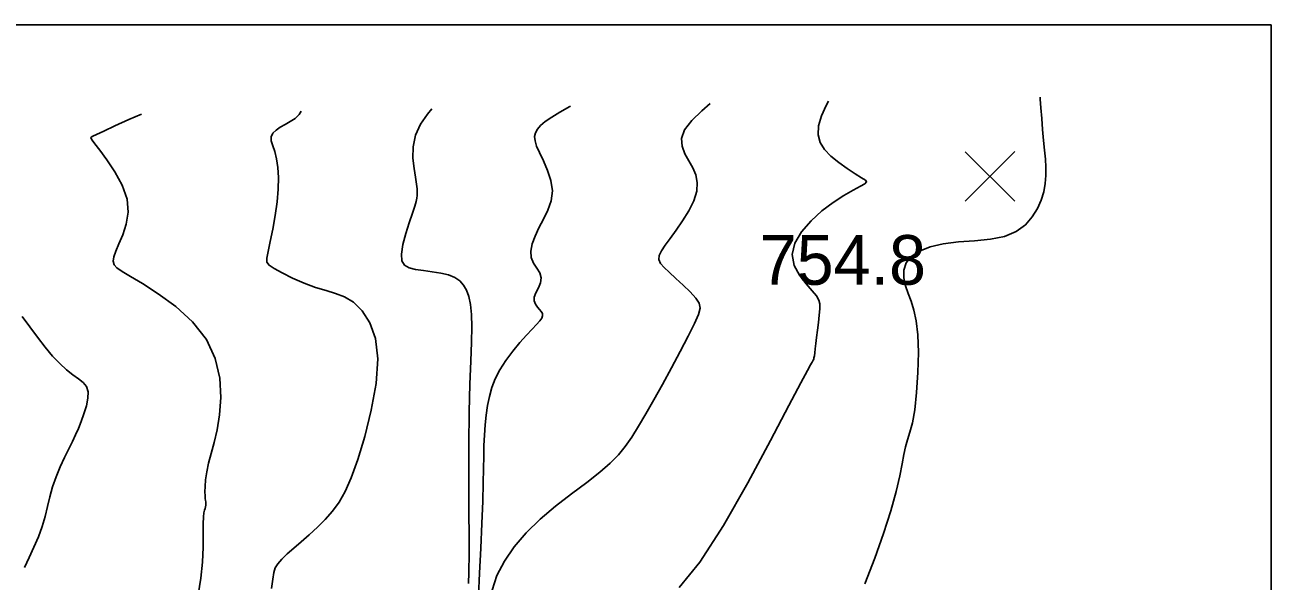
# Model space of a CAD drawing. Extents: x 2566142 to 2571431, y 418755 to 421584.
# Drawn here: x 2571031.7 to 2571407.8, y 421393.7 to 421561.7 of the extents above; entities that cross this region are included whole.
import ezdxf

# ---------------------------------------------------------------- set-up
doc = ezdxf.new("R2010")
doc.units = 0
for name, color, linetype in [('Contour_ADS_Major', 7, 'Continuous'), ('Contour_ADS_Minor', 7, 'Continuous'), ('Contour_ADS_Spot_Elevation', 7, 'Continuous'), ('Contour_ADS_State_Plane_Border', 7, 'Continuous')]:
    doc.layers.add(name, color=color, linetype=linetype)

# ---------------------------------------------------------------- blocks, each defined once
blk = doc.blocks.new('S750')
at = {"layer": 'Contour_ADS_Spot_Elevation'}
for p, q in [((-0.5, 0.498), (0.5, -0.498)), ((-0.498, -0.5), (0.498, 0.5))]:
    blk.add_line(p, q, dxfattribs=at)

msp = doc.modelspace()

# ---------------------------------------------------------------- linework, layer by layer
at = {"layer": 'Contour_ADS_Major'}
msp.add_lwpolyline([(2571168.56, 421389.26), (2571168.9, 421396.14), (2571169.26, 421403.66), (2571169.6, 421411.13), (2571169.87, 421417.87), (2571170.02, 421423.35), (2571170.11, 421427.74), (2571170.16, 421431.4), (2571170.24, 421434.66), (2571170.38, 421437.81), (2571170.6, 421440.88), (2571170.91, 421443.86), (2571171.33, 421446.73), (2571171.88, 421449.47), (2571172.63, 421452.15), (2571173.67, 421454.82), (2571175.07, 421457.55), (2571176.88, 421460.37), (2571178.95, 421463.17), (2571181.08, 421465.78), (2571183.08, 421468.04), (2571184.76, 421469.85), (2571186.11, 421471.24), (2571187.09, 421472.32), (2571187.7, 421473.17), (2571187.94, 421473.88), (2571187.86, 421474.51), (2571187.52, 421475.12), (2571186.99, 421475.76), (2571186.35, 421476.48), (2571185.76, 421477.32), (2571185.39, 421478.31), (2571185.42, 421479.47), (2571185.93, 421480.82), (2571186.68, 421482.3), (2571187.32, 421483.83), (2571187.53, 421485.34), (2571187.06, 421486.78), (2571186.17, 421488.21), (2571185.2, 421489.73), (2571184.52, 421491.43), (2571184.4, 421493.37), (2571184.82, 421495.54), (2571185.67, 421497.89), (2571186.84, 421500.39), (2571188.22, 421503), (2571189.54, 421505.73), (2571190.53, 421508.58), (2571190.89, 421511.57), (2571190.45, 421514.67), (2571189.44, 421517.75), (2571188.17, 421520.62), (2571186.97, 421523.11), (2571186.12, 421525.09), (2571185.65, 421526.66), (2571185.54, 421527.94), (2571185.78, 421529.07), (2571186.36, 421530.17), (2571187.33, 421531.29), (2571188.75, 421532.49), (2571190.68, 421533.82), (2571193.16, 421535.32), (2571196.14, 421537.02), (2571196.4, 421537.17)], dxfattribs=at)
at = {"layer": 'Contour_ADS_Minor'}
for points in [[(2571172.69, 421391.03), (2571174.17, 421395.42), (2571176.41, 421399.78), (2571179.38, 421404.1), (2571183.01, 421408.35), (2571187.21, 421412.46), (2571191.88, 421416.41), (2571196.68, 421420.12), (2571201.26, 421423.54), (2571205.24, 421426.6), (2571208.37, 421429.3), (2571210.83, 421431.82), (2571212.89, 421434.38), (2571214.83, 421437.21), (2571216.88, 421440.5), (2571219.11, 421444.25), (2571221.5, 421448.47), (2571224.08, 421453.11), (2571226.81, 421458.11), (2571229.49, 421463.11), (2571231.9, 421467.71), (2571233.8, 421471.51), (2571235, 421474.23), (2571235.47, 421476.15), (2571235.2, 421477.67), (2571234.19, 421479.2), (2571232.51, 421481.05), (2571230.4, 421483.1), (2571228.18, 421485.15), (2571226.15, 421486.98), (2571224.58, 421488.46), (2571223.54, 421489.68), (2571223.05, 421490.81), (2571223.14, 421492.01), (2571223.8, 421493.45), (2571224.94, 421495.17), (2571226.47, 421497.22), (2571228.26, 421499.65), (2571230.2, 421502.47), (2571232.04, 421505.5), (2571233.55, 421508.57), (2571234.48, 421511.46), (2571234.64, 421514.05), (2571234.17, 421516.37), (2571233.25, 421518.54), (2571232.09, 421520.64), (2571230.89, 421522.78), (2571230.02, 421525.02), (2571229.84, 421527.41), (2571230.74, 421530.01), (2571232.93, 421532.83), (2571235.98, 421535.74), (2571238.56, 421537.97)], [(2571229.19, 421391.76), (2571235.37, 421399.49), (2571242.49, 421410.56), (2571249.88, 421423.44), (2571256.75, 421436.16), (2571262.27, 421446.71), (2571265.88, 421453.6), (2571267.87, 421457.35), (2571268.76, 421458.99), (2571269.07, 421459.53), (2571269.25, 421459.82), (2571269.39, 421460.06), (2571269.5, 421460.25), (2571269.59, 421460.41), (2571269.68, 421460.58), (2571269.76, 421460.81), (2571269.85, 421461.19), (2571269.96, 421461.79), (2571270.09, 421462.68), (2571270.24, 421463.89), (2571270.43, 421465.43), (2571270.65, 421467.31), (2571270.92, 421469.51), (2571271.19, 421471.84), (2571271.42, 421474.07), (2571271.57, 421475.98), (2571271.57, 421477.43), (2571271.3, 421478.61), (2571270.6, 421479.83), (2571269.33, 421481.38), (2571267.46, 421483.47), (2571265.45, 421486.07), (2571263.86, 421489.07), (2571263.27, 421492.34), (2571264.09, 421495.77), (2571266.12, 421499.22), (2571268.96, 421502.51), (2571272.26, 421505.51), (2571275.65, 421508.07), (2571278.88, 421510.17), (2571281.71, 421511.81), (2571283.89, 421512.98), (2571285.23, 421513.73), (2571285.71, 421514.24), (2571285.35, 421514.76), (2571284.17, 421515.53), (2571282.24, 421516.73), (2571279.85, 421518.3), (2571277.31, 421520.12), (2571274.95, 421522.07), (2571273.06, 421524.07), (2571271.76, 421526.19), (2571271.12, 421528.52), (2571271.23, 421531.18), (2571272.11, 421534.19), (2571273.5, 421537.35), (2571274.18, 421538.65)], [(2571297.64, 421489.8), (2571299.23, 421491.74), (2571301.67, 421493.39), (2571304.91, 421494.7), (2571308.88, 421495.62), (2571313.46, 421496.13), (2571318.32, 421496.48), (2571323.08, 421496.95), (2571327.36, 421497.83), (2571330.88, 421499.32), (2571333.64, 421501.34), (2571335.75, 421503.7), (2571337.33, 421506.22), (2571338.45, 421508.77), (2571339.21, 421511.3), (2571339.65, 421513.8), (2571339.83, 421516.25), (2571339.83, 421518.67), (2571339.69, 421521.15), (2571339.45, 421523.81), (2571339.16, 421526.76), (2571338.85, 421530.06), (2571338.57, 421533.45), (2571338.32, 421536.62), (2571338.13, 421539.25), (2571338.1, 421539.87)], [(2571086.01, 421420.66), (2571086.06, 421422.28), (2571086.23, 421424.32), (2571086.57, 421426.71), (2571087.14, 421429.37), (2571087.93, 421432.29), (2571088.85, 421435.57), (2571089.73, 421439.39), (2571090.44, 421443.91), (2571090.78, 421449.2), (2571090.47, 421455), (2571089.14, 421460.96), (2571086.48, 421466.73), (2571082.31, 421472.01), (2571077.2, 421476.64), (2571071.89, 421480.52), (2571067.14, 421483.56), (2571063.52, 421485.72), (2571061.02, 421487.21), (2571059.43, 421488.3), (2571058.58, 421489.26), (2571058.29, 421490.35), (2571058.48, 421491.69), (2571059.09, 421493.4), (2571060.05, 421495.57), (2571061.22, 421498.29), (2571062.29, 421501.51), (2571062.86, 421505.13), (2571062.53, 421509.09), (2571061.07, 421513.25), (2571058.86, 421517.33), (2571056.41, 421520.98), (2571054.26, 421523.88), (2571052.81, 421525.78), (2571051.99, 421526.87), (2571051.64, 421527.38), (2571051.55, 421527.59), (2571051.65, 421527.75), (2571052.14, 421528.03), (2571053.33, 421528.6), (2571055.5, 421529.63), (2571058.85, 421531.19), (2571063.04, 421533.08), (2571066.86, 421534.69)], [(2571124.57, 421414.9), (2571126.55, 421417.61), (2571128.37, 421420.82), (2571130.19, 421424.96), (2571132.13, 421430.42), (2571134.24, 421437.4), (2571136.22, 421445.32), (2571137.67, 421453.39), (2571138.18, 421460.81), (2571137.48, 421466.94), (2571135.79, 421471.76), (2571133.46, 421475.38), (2571130.83, 421477.93), (2571128.17, 421479.57), (2571125.45, 421480.62), (2571122.57, 421481.44), (2571119.42, 421482.37), (2571115.96, 421483.68), (2571112.49, 421485.23), (2571109.34, 421486.78), (2571106.89, 421488.11), (2571105.37, 421489.09), (2571104.7, 421490.01), (2571104.66, 421491.26), (2571105.07, 421493.24), (2571105.72, 421496.23), (2571106.48, 421499.97), (2571107.22, 421504.1), (2571107.82, 421508.25), (2571108.16, 421512.11), (2571108.23, 421515.58), (2571108.06, 421518.64), (2571107.66, 421521.26), (2571107.07, 421523.43), (2571106.47, 421525.2), (2571106.05, 421526.67), (2571106.02, 421527.9), (2571106.53, 421528.97), (2571107.48, 421529.93), (2571108.77, 421530.81), (2571110.24, 421531.64), (2571111.77, 421532.47), (2571113.23, 421533.43), (2571114.46, 421534.62), (2571115.02, 421535.61)], [(2571165.57, 421393), (2571165.61, 421394.02), (2571165.67, 421395.31), (2571165.72, 421397.45), (2571165.75, 421401.06), (2571165.75, 421406.77), (2571165.7, 421414.91), (2571165.65, 421424.69), (2571165.65, 421435.01), (2571165.74, 421444.82), (2571165.97, 421453.22), (2571166.25, 421460.19), (2571166.49, 421465.91), (2571166.59, 421470.55), (2571166.48, 421474.28), (2571166.16, 421477.25), (2571165.63, 421479.62), (2571164.93, 421481.53), (2571164.05, 421483.11), (2571162.92, 421484.4), (2571161.46, 421485.42), (2571159.57, 421486.2), (2571157.22, 421486.75), (2571154.62, 421487.16), (2571152, 421487.5), (2571149.61, 421487.87), (2571147.69, 421488.36), (2571146.29, 421489.15), (2571145.48, 421490.46), (2571145.31, 421492.49), (2571145.77, 421495.34), (2571146.65, 421498.65), (2571147.7, 421501.96), (2571148.66, 421504.84), (2571149.34, 421506.92), (2571149.75, 421508.34), (2571149.96, 421509.35), (2571150.06, 421510.17), (2571150.1, 421511.05), (2571150.05, 421512.15), (2571149.9, 421513.63), (2571149.59, 421515.65), (2571149.16, 421518.31), (2571148.82, 421521.45), (2571148.86, 421524.87), (2571149.56, 421528.35), (2571151.09, 421531.69), (2571153.17, 421534.74), (2571154.55, 421536.37)], [(2571285.16, 421392.94), (2571288.21, 421400.67), (2571290.85, 421408.13), (2571293.01, 421414.96), (2571294.65, 421420.83), (2571295.74, 421425.5), (2571296.44, 421429.12), (2571296.94, 421431.96), (2571297.43, 421434.29), (2571298.07, 421436.39), (2571298.81, 421438.67), (2571299.57, 421441.56), (2571300.28, 421445.49), (2571300.84, 421450.7), (2571301.22, 421456.68), (2571301.35, 421462.72), (2571301.18, 421468.12), (2571300.7, 421472.35), (2571299.98, 421475.59), (2571299.13, 421478.21), (2571298.24, 421480.56), (2571297.45, 421482.93), (2571296.94, 421485.32), (2571296.93, 421487.63), (2571297.64, 421489.8)], [(2571031.6, 421397.88), (2571032.97, 421400.88), (2571034.4, 421403.99), (2571035.75, 421407.15), (2571036.91, 421410.27), (2571037.79, 421413.29), (2571038.49, 421416.25), (2571039.17, 421419.19), (2571040.01, 421422.17), (2571041.09, 421425.21), (2571042.35, 421428.22), (2571043.67, 421431.07), (2571044.92, 421433.64), (2571046, 421435.87), (2571046.95, 421437.88), (2571047.82, 421439.84), (2571048.67, 421441.93), (2571049.52, 421444.25), (2571050.24, 421446.66), (2571050.7, 421448.95), (2571050.73, 421450.93), (2571050.23, 421452.46), (2571049.25, 421453.68), (2571047.87, 421454.81), (2571046.18, 421456.04), (2571044.27, 421457.57), (2571042.2, 421459.45), (2571040.01, 421461.7), (2571037.77, 421464.34), (2571035.51, 421467.35), (2571033.21, 421470.53), (2571030.86, 421473.64)], [(2571083.94, 421389.59), (2571084.8, 421394.6), (2571085.29, 421399.5), (2571085.48, 421404.02), (2571085.51, 421407.94), (2571085.5, 421411.02), (2571085.58, 421413.1), (2571085.72, 421414.38), (2571085.89, 421415.13), (2571086.06, 421415.64), (2571086.2, 421416.13), (2571086.29, 421416.64), (2571086.32, 421417.15), (2571086.31, 421417.64), (2571086.24, 421418.12), (2571086.14, 421418.7), (2571086.05, 421419.5), (2571086.01, 421420.66)], [(2571106.14, 421391.51), (2571106.48, 421394.36), (2571106.78, 421396.31), (2571107.22, 421397.73), (2571107.99, 421398.97), (2571109.21, 421400.36), (2571110.86, 421401.93), (2571112.85, 421403.69), (2571115.09, 421405.62), (2571117.49, 421407.72), (2571119.95, 421409.98), (2571122.35, 421412.38), (2571124.57, 421414.9)]]:
    msp.add_lwpolyline(points, dxfattribs=at)
at = {"layer": 'Contour_ADS_State_Plane_Border'}
msp.add_lwpolyline([(2566164.43, 418777.5), (2571407.81, 418777.5), (2571407.81, 421561.67), (2566164.43, 421561.67), (2566164.43, 418777.5)], close=True, dxfattribs=at)

# ---------------------------------------------------------------- block references
at = {"layer": 'Contour_ADS_Spot_Elevation', "xscale": 15, "yscale": 15}
msp.add_blockref('S750', (2571322.97, 421515.91), dxfattribs=at)

# ---------------------------------------------------------------- texts
at = {"layer": 'Contour_ADS_Spot_Elevation'}
msp.add_text('754.8', height=15, dxfattribs=at).set_placement((2571253.46, 421483.21))

doc.saveas('drawing.dxf')
